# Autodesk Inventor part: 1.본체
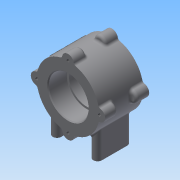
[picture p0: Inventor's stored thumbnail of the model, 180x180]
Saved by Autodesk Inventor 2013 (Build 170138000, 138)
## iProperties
Created: 2015-03
Part Number: 1.본체
Material: 일반
Document SubType Name: Modeling
Designer: Administrator
Density: 1 g/cm^3
Mass: 166.233 g
Surface Area: 333.35 cm^2
Volume: 166.233 cm^3
Author: Administrator
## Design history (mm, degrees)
sketch "스케치1"
  geometry: L1 (-26, 0)-(26, 0); L2 (-25, 23.5)-(-4.3, 23.5); L3 (-4, 23.2)-(-4, 21); L4 (-4, 21)-(4, 21); L5 (4, 21)-(4, 23.2); L6 (4.3, 23.5)-(25, 23.5); L7 (26, 24.5)-(26, 37); L8 (26, 37)-(-26, 37); L9 (-26, 37)-(-26, 24.5); L10 (-25, 23.5)-(-26, 24.5); L11 (25, 23.5)-(26, 24.5); A1 r 0.3 centre (-4.3, 23.2) between (-4, 23.2) and (-4.3, 23.5); A2 r 0.3 centre (4.3, 23.2) between (4.3, 23.5) and (4, 23.2); 4 further points
  constraints: 22 end point, 6 parallel, 4 point on circle, 4 point on line, 4 tangent, 2 centre point, 2 collinear, 2 vertical alignment, 1 coincident, 1 equal radius, 1 horizontal, 1 midpoint, 1 perpendicular
  dimensions: "d1" = 52 distance of L1.start L1.end; "d3" = 42 diameter of L4 L1; "d4" = 47 diameter of L2 L1; "d5" = 22 distance between parallel lines of L3 L9; "d6" = 22 distance between parallel lines of L5 L7; "d7" = 74 diameter of L8 L1; "d8" = 0.3 radius of A1; "d9" = 1 distance of L2.start point (-26, 23.5); "d10" = 45 deg angle of L2 L10; "d11" = 1 distance of L6.end point (26, 23.5) (= d9); "d12" = 45 deg angle of L6 L11 (= d10)
revolve "회전1" sketch "스케치1" stored, may be unused: angle "d13" = 90 deg
sketch "스케치3"
  geometry: C1 r 7 at (0, 37); C2 r 7 at (-37, 0); C3 r 7 at (0, -37); C4 r 7 at (37, 0); 2 further points
  constraints: 4 centre point, 2 vertical alignment, 10 other
  dimensions: "d14" = 14 diameter of C1; "d18" = 360 deg dimension on point (0, 0) C1.centre (derived)
extrude "돌출1" join sketch "스케치3" distance "d20" = 15; taper "d21" = 0 deg
hole "구멍1" diameter "d24" = 3.459; stored, may be unused: countersink angle "d28" = 90 deg, drill point angle "d30" = 118 deg; dims "d22" = 10, "d23" = 10, "d25" = 8, "d26" = 4, "d27" = 2, "d29" = 11
sketch "스케치4"
  geometry: L1 (19, -16)-(29, -16); L2 (29, -16)-(29, -56); L3 (29, -56)-(19, -56); L4 (19, -56)-(19, -16); L5 (24, -16)-(24, -56); L6 (0, 0)-(0, -16); L7 (-19, -16)-(-29, -16); L8 (-29, -16)-(-29, -56); L9 (-29, -56)-(-19, -56); L10 (-19, -56)-(-19, -16); L11 (-24, -16)-(-24, -56)
  constraints: 22 end point, 6 symmetric about line, 3 parallel, 2 midpoint, 1 horizontal, 1 horizontal alignment, 1 perpendicular
  dimensions: "d34" = 56 distance from line of L3 L6.start; "d36" = 10 distance between parallel lines of L4 L2; "d38" = 24 distance from line of L6.start L5; "d39" = 40 distance between parallel lines of L3 L1
extrude "돌출2" join sketch "스케치4" stored distance "d40" = 40; taper "d41" = 0 deg
fillet "모깎기1" dims "d42" = 5
hole "구멍2" diameter "d45" = 4.134; stored, may be unused: countersink angle "d49" = 90 deg, drill point angle "d51" = 118 deg; dims "d46" = 6, "d47" = 4, "d48" = 2, "d50" = 8, "d57" = 10, "d58" = 10
fillet "모깎기2" dims "d52" = 3
fillet "모깎기3" dims "d53" = 3
node "작업 평면2"
  node "작업 평면1"
sketch "스케치6"
  geometry: 2 further points
  constraints: 1 coincident, 1 other
feature "엠보싱1" sketch "스케치6" dims "d1" = 52, "d3" = 42, "d4" = 47, "d5" = 22, "d6" = 22, "d7" = 74, "d8" = 0.3, "d9" = 1, "d10" = 45 deg, "d11" = 1 (= d9), "d12" = 45 deg (= d10), "d55" = 0.5, "d56" = 0
node "솔리드1"
pattern_circular "원형 패턴1" dims angle "d32" = 360 deg
mirror "대칭1"
mirror "대칭2"
mirror "대칭3"
node "작업축2"
other parameters: "d54" = 45 deg
